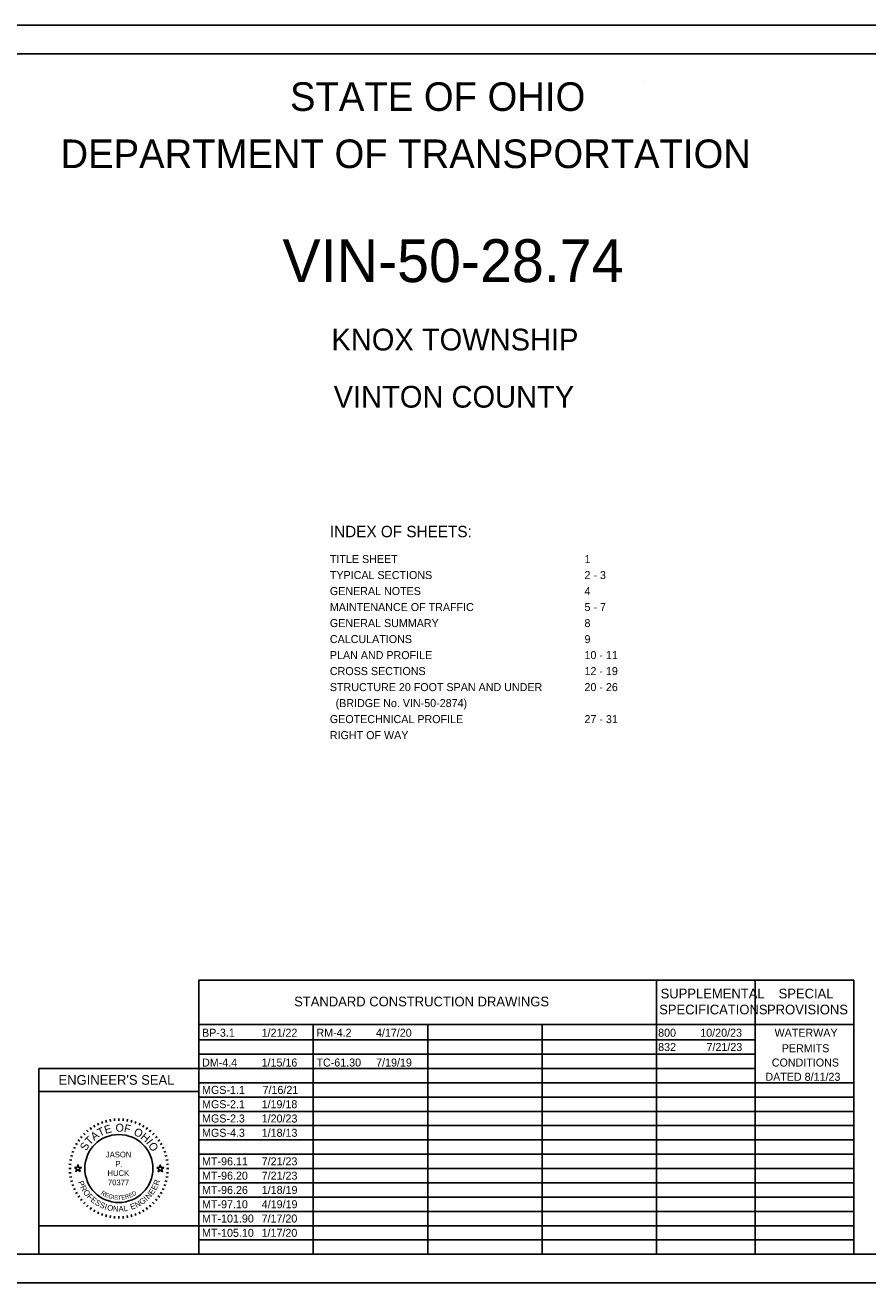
# Model space of a CAD drawing. Extents: x -8.2 to 34, y 0 to 22.
# Drawn here: x 9.34 to 24.07, y 0 to 22 of the extents above; entities that cross this region are included whole.
import ezdxf

# ---------------------------------------------------------------- set-up
doc = ezdxf.new("R2010")
doc.units = 0
for name, color, linetype in [('Default', 7, 'Continuous'), ('SH_Border', 7, 'Continuous'), ('SH_Cut_Line', 7, 'Continuous'), ('SH_Data', 7, 'Continuous'), ('SH_Text', 7, 'Continuous')]:
    doc.layers.add(name, color=color, linetype=linetype)

msp = doc.modelspace()

# ---------------------------------------------------------------- linework, layer by layer
at = {"layer": 'Default'}
for p, q in [((16.952, 21), (16.952, 21)), ((16.952, 21), (16.952, 21)), ((16.952, 21), (16.952, 21)), ((16.952, 21), (16.952, 21)), ((20.141, 21), (20.141, 21))]:
    msp.add_line(p, q, dxfattribs=at)
at = {"layer": 'SH_Border'}
msp.add_lwpolyline([(1.5, 21.5), (33.5, 21.5), (33.5, 0.5), (1.5, 0.5)], close=True, dxfattribs=at)
at = {"layer": 'SH_Cut_Line'}
msp.add_lwpolyline([(0, 0), (34, 0), (34, 22), (0, 22)], close=True, dxfattribs=at)
at = {"layer": 'SH_Data'}
for p, q in [((12.375, 5.292), (23.825, 5.292)), ((12.375, 0.5), (12.375, 5.292)), ((20.375, 0.5), (20.375, 5.292)), ((22.1, 0.5), (22.1, 5.292)), ((23.825, 0.5), (23.825, 5.292)), ((12.375, 4.521), (23.825, 4.521)), ((14.375, 0.5), (14.375, 4.521)), ((16.375, 0.5), (16.375, 4.521)), ((18.375, 0.5), (18.375, 4.521)), ((12.375, 4.25), (22.1, 4.25)), ((12.375, 4), (22.1, 4)), ((12.375, 3.75), (9.575, 3.75)), ((9.575, 3.75), (9.575, 0.5)), ((12.375, 3.75), (22.1, 3.75)), ((12.375, 0.5), (12.375, 3.75)), ((12.375, 3.35), (9.575, 3.35)), ((12.375, 3.5), (23.825, 3.5)), ((12.375, 3.25), (23.825, 3.25)), ((10.823, 2.862), (10.83, 2.822)), ((10.899, 2.872), (10.902, 2.832)), ((10.975, 2.875), (10.975, 2.835)), ((11.051, 2.872), (11.048, 2.832)), ((11.127, 2.862), (11.12, 2.822)), ((12.375, 3), (23.825, 3)), ((10.412, 2.67), (10.438, 2.64)), ((10.473, 2.717), (10.496, 2.684)), ((10.537, 2.758), (10.557, 2.723)), ((10.605, 2.793), (10.622, 2.757)), ((10.676, 2.822), (10.689, 2.785)), ((10.748, 2.845), (10.759, 2.807)), ((11.201, 2.845), (11.191, 2.807)), ((11.274, 2.822), (11.26, 2.785)), ((11.345, 2.793), (11.328, 2.757)), ((11.412, 2.758), (11.392, 2.723)), ((11.477, 2.717), (11.454, 2.684)), ((11.537, 2.67), (11.512, 2.64)), ((12.375, 2.75), (23.825, 2.75)), ((10.217, 2.438), (10.252, 2.418)), ((10.258, 2.502), (10.291, 2.479)), ((10.304, 2.562), (10.335, 2.537)), ((10.356, 2.619), (10.384, 2.59)), ((11.593, 2.619), (11.565, 2.59)), ((11.645, 2.562), (11.614, 2.537)), ((11.692, 2.502), (11.659, 2.479)), ((11.733, 2.438), (11.698, 2.418)), ((12.375, 2.5), (23.825, 2.5)), ((10.13, 2.226), (10.168, 2.216)), ((10.153, 2.299), (10.19, 2.286)), ((10.182, 2.37), (10.218, 2.353)), ((11.768, 2.37), (11.732, 2.353)), ((11.797, 2.299), (11.759, 2.286)), ((11.82, 2.226), (11.781, 2.216)), ((12.375, 2.25), (23.825, 2.25)), ((10.1, 2), (10.14, 2)), ((10.103, 2.076), (10.143, 2.073)), ((10.113, 2.152), (10.152, 2.145)), ((11.836, 2.152), (11.797, 2.145)), ((11.846, 2.076), (11.807, 2.073)), ((11.85, 2), (11.81, 2)), ((12.375, 2), (23.825, 2)), ((10.103, 1.924), (10.143, 1.927)), ((10.113, 1.848), (10.152, 1.855)), ((10.13, 1.774), (10.168, 1.784)), ((11.82, 1.774), (11.781, 1.784)), ((11.836, 1.848), (11.797, 1.855)), ((11.846, 1.924), (11.807, 1.927)), ((10.153, 1.701), (10.19, 1.714)), ((10.182, 1.63), (10.218, 1.647)), ((10.217, 1.563), (10.252, 1.583)), ((11.733, 1.563), (11.698, 1.583)), ((11.768, 1.63), (11.732, 1.647)), ((11.797, 1.701), (11.759, 1.714)), ((12.375, 1.75), (23.825, 1.75)), ((10.258, 1.498), (10.291, 1.521)), ((10.304, 1.438), (10.335, 1.463)), ((10.356, 1.381), (10.384, 1.41)), ((10.412, 1.33), (10.438, 1.36)), ((11.537, 1.33), (11.512, 1.36)), ((11.593, 1.381), (11.565, 1.41)), ((11.645, 1.438), (11.614, 1.463)), ((11.692, 1.498), (11.659, 1.521)), ((12.375, 1.5), (23.825, 1.5)), ((10.473, 1.283), (10.496, 1.316)), ((10.537, 1.242), (10.557, 1.277)), ((10.605, 1.207), (10.622, 1.243)), ((10.676, 1.178), (10.689, 1.215)), ((10.748, 1.155), (10.759, 1.193)), ((10.823, 1.138), (10.83, 1.178)), ((10.899, 1.128), (10.902, 1.168)), ((10.975, 1.125), (10.975, 1.165)), ((11.051, 1.128), (11.048, 1.168)), ((11.127, 1.138), (11.12, 1.178)), ((11.201, 1.155), (11.191, 1.193)), ((11.274, 1.178), (11.26, 1.215)), ((11.345, 1.207), (11.328, 1.243)), ((11.412, 1.242), (11.392, 1.277)), ((11.477, 1.283), (11.454, 1.316)), ((12.375, 1.25), (23.825, 1.25)), ((12.375, 1), (23.825, 1)), ((12.375, 0.75), (23.825, 0.75)), ((12.375, 0.5), (9.575, 0.5))]:
    msp.add_line(p, q, dxfattribs=at)
for points in [[(10.198, 2.02), (10.245, 2.02), (10.26, 2.065), (10.274, 2.02), (10.321, 2.02), (10.283, 1.992), (10.298, 1.948), (10.26, 1.975), (10.222, 1.948), (10.236, 1.992)], [(11.638, 2.015), (11.684, 2.015), (11.699, 2.059), (11.713, 2.015), (11.76, 2.015), (11.722, 1.987), (11.737, 1.942), (11.699, 1.97), (11.661, 1.942), (11.675, 1.987)], [(12.375, 0.5), (12.375, 1), (9.575, 1), (9.575, 0.5)]]:
    msp.add_lwpolyline(points, close=True, dxfattribs=at)
msp.add_circle((10.975, 2), 0.595, dxfattribs=at)

# ---------------------------------------------------------------- texts
for s, height, p in [("ENGINEER'S SEAL", 0.17, (9.92, 3.465)), ('JASON', 0.1, (10.748, 2.194)), ('P.', 0.1, (10.915, 2.031)), ('HUCK', 0.1, (10.777, 1.869)), ('70377', 0.1, (10.784, 1.706))]:
    msp.add_text(s, height=height, dxfattribs=at).set_placement(p)
for s, height, rotation, p in [('T', 0.14, 25.7167, (10.641, 2.554)), ('E', 0.14, 15.7571, (10.742, 2.603)), ('O', 0.14, 359.7812, (10.917, 2.644)), ('F', 0.14, 347.4362, (11.056, 2.642)), ('O', 0.14, 332.2586, (11.221, 2.598)), ('S', 0.14, 57.1924, (10.401, 2.298)), ('T', 0.14, 46.4344, (10.466, 2.4)), ('A', 0.14, 36.4747, (10.543, 2.482)), ('H', 0.14, 319.9136, (11.343, 2.532)), ('I', 0.14, 308.367, (11.442, 2.447)), ('O', 0.14, 303.1491, (11.481, 2.403)), ('P', 0.1, 291.494, (10.257, 1.762)), ('R', 0.1, 69.2322, (11.666, 1.694)), ('R', 0.1, 298.7311, (10.293, 1.673)), ('O', 0.1, 306.4666, (10.343, 1.585)), ('F', 0.1, 314.7068, (10.409, 1.498)), ('R', 0.075, 327.8239, (10.655, 1.554)), ('E', 0.075, 337.7777, (10.719, 1.513)), ('G', 0.075, 344.2727, (10.783, 1.485)), ('R', 0.075, 17.6836, (11.093, 1.463)), ('E', 0.075, 23.3052, (11.166, 1.486)), ('D', 0.075, 31.466, (11.23, 1.514)), ('N', 0.1, 47.0224, (11.499, 1.455)), ('E', 0.1, 54.758, (11.568, 1.531)), ('E', 0.1, 61.9951, (11.622, 1.609)), ('E', 0.1, 321.4393, (10.472, 1.435)), ('S', 0.1, 328.6764, (10.547, 1.377)), ('S', 0.1, 335.9134, (10.629, 1.328)), ('I', 0.1, 343.1505, (10.716, 1.289)), ('O', 0.1, 346.8859, (10.763, 1.274)), ('I', 0.075, 350.6464, (10.862, 1.463)), ('N', 0.1, 355.1261, (10.869, 1.251)), ('S', 0.075, 353.7858, (10.89, 1.458)), ('T', 0.075, 3.0061, (10.96, 1.451)), ('A', 0.1, 2.8617, (10.971, 1.244)), ('E', 0.075, 8.9826, (11.024, 1.453)), ('L', 0.1, 10.0987, (11.066, 1.249)), ('E', 0.1, 20.0742, (11.195, 1.277)), ('N', 0.1, 27.3113, (11.284, 1.31)), ('G', 0.1, 35.0469, (11.374, 1.358)), ('I', 0.1, 43.287, (11.462, 1.422))]:
    msp.add_text(s, height=height, rotation=rotation, dxfattribs=at).set_placement(p)
at = {"layer": 'SH_Text'}
for s, height, p in [('STATE OF OHIO', 0.5, (13.968, 20.5)), ('DEPARTMENT OF TRANSPORTATION', 0.5, (9.955, 19.5)), ('VIN-50-28.74', 0.75, (13.835, 17.505)), ('KNOX TOWNSHIP', 0.38, (14.692, 16.31)), ('VINTON COUNTY', 0.38, (14.731, 15.31)), ('INDEX OF SHEETS:', 0.2, (14.665, 13.042)), ('TITLE SHEET', 0.14, (14.665, 12.591)), ('1', 0.14, (19.117, 12.591)), ('TYPICAL SECTIONS', 0.14, (14.665, 12.311)), ('2 - 3', 0.14, (19.117, 12.311)), ('GENERAL NOTES', 0.14, (14.665, 12.031)), ('4', 0.14, (19.117, 12.031)), ('MAINTENANCE OF TRAFFIC', 0.14, (14.665, 11.751)), ('5 - 7', 0.14, (19.117, 11.751)), ('GENERAL SUMMARY', 0.14, (14.665, 11.471)), ('8', 0.14, (19.117, 11.471)), ('CALCULATIONS', 0.14, (14.665, 11.191)), ('9', 0.14, (19.117, 11.191)), ('PLAN AND PROFILE', 0.14, (14.665, 10.911)), ('10 - 11', 0.14, (19.117, 10.911)), ('CROSS SECTIONS', 0.14, (14.665, 10.631)), ('12 - 19', 0.14, (19.117, 10.631)), ('STRUCTURE 20 FOOT SPAN AND UNDER', 0.14, (14.665, 10.351)), ('20 - 26', 0.14, (19.117, 10.351)), ('(BRIDGE No. VIN-50-2874)', 0.14, (14.765, 10.071)), ('GEOTECHNICAL PROFILE', 0.14, (14.665, 9.791)), ('27 - 31', 0.14, (19.117, 9.791)), ('RIGHT OF WAY', 0.14, (14.665, 9.511)), ('SUPPLEMENTAL', 0.17, (20.448, 4.976)), ('SPECIAL', 0.17, (22.511, 4.976)), ('STANDARD CONSTRUCTION DRAWINGS', 0.17, (14.04, 4.836)), ('SPECIFICATIONS', 0.17, (20.423, 4.696)), ('PROVISIONS', 0.17, (22.309, 4.696)), ('BP-3.1', 0.14, (12.43, 4.305)), ('1/21/22', 0.14, (13.472, 4.305)), ('RM-4.2', 0.14, (14.43, 4.305)), ('4/17/20', 0.14, (15.471, 4.305)), ('800', 0.14, (20.405, 4.305)), ('10/20/23', 0.14, (21.142, 4.305)), ('WATERWAY', 0.14, (22.44, 4.305)), ('832', 0.14, (20.405, 4.055)), ('7/21/23', 0.14, (21.251, 4.055)), ('PERMITS', 0.14, (22.566, 4.034)), ('DM-4.4', 0.14, (12.43, 3.784)), ('1/15/16', 0.14, (13.471, 3.784)), ('TC-61.30', 0.14, (14.43, 3.784)), ('7/19/19', 0.14, (15.474, 3.784)), ('CONDITIONS', 0.14, (22.392, 3.784)), ('DATED 8/11/23', 0.14, (22.28, 3.534)), ('MGS-1.1', 0.14, (12.43, 3.305)), ('7/16/21', 0.14, (13.488, 3.305)), ('MGS-2.1', 0.14, (12.43, 3.055)), ('1/19/18', 0.14, (13.471, 3.055)), ('MGS-2.3', 0.14, (12.43, 2.805)), ('1/20/23', 0.14, (13.473, 2.805)), ('MGS-4.3', 0.14, (12.43, 2.555)), ('1/18/13', 0.14, (13.473, 2.555)), ('7/21/23', 0.14, (13.473, 2.055)), ('MT-96.11', 0.14, (12.43, 2.055)), ('MT-96.20', 0.14, (12.43, 1.805)), ('7/21/23', 0.14, (13.473, 1.805)), ('MT-96.26', 0.14, (12.43, 1.555)), ('1/18/19', 0.14, (13.474, 1.555)), ('MT-97.10', 0.14, (12.43, 1.305)), ('4/19/19', 0.14, (13.474, 1.305)), ('MT-101.90', 0.14, (12.43, 1.055)), ('7/17/20', 0.14, (13.471, 1.055)), ('MT-105.10', 0.14, (12.43, 0.805)), ('1/17/20', 0.14, (13.471, 0.805))]:
    msp.add_text(s, height=height, dxfattribs=at).set_placement(p)

doc.saveas('drawing.dxf')
